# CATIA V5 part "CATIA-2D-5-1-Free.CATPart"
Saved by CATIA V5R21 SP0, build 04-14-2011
Part number: CATIA-2D-5-1-Free
Bounding box of the stored display mesh (mm): x -146.99 to 61.498, y -1 to 1, z -11.995 to 34.997
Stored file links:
  C:\Users\Rasoul Mohammadi\Desktop\CATIA-Free\2D\CATIA-2D-5-1-Free.CATPart
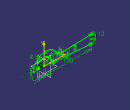
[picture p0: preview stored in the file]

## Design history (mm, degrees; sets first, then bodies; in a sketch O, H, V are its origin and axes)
Body1 (main body)
  Sketch1 on zx-plane, origin (0, 0, 0), H (-1, 0, 0), V (0, 0, 1)
    arc A1 centre (0, 0) radius 22 from (21.9106, 1.9813) to (-21.4243, 5) ccw
    arc A2 centre (5, 0) radius 35 from (36.7634, 14.6999) to (-30, 0) ccw
    point P1 (5, 0)
    arc A3 centre (135, 0) radius 12 from (133.9541, -11.9543) to (134.5812, 11.9927) ccw
    point P2 (135, 0)
    line L1 (26.4545, -2.5493) -> (133.9541, -11.9543)
    point P3 (133.9541, -11.9543)
    line L2 (46.1877, 8.9059) -> (134.5812, 11.9927)
    point P5 (-30, 0)
    line L3 (-30, 0) -> (-14, 0)
    line L4 (-14, 0) -> (-14, 5)
    line L5 (-14, 5) -> (-21.4243, 5)
    point P9 (133.9541, -11.9543)
    arc A4 centre (26.8903, 2.4316) radius 5 from (21.9106, 1.9813) to (26.4545, -2.5493) ccw
    arc A5 centre (45.8387, 18.8998) radius 10 from (36.7634, 14.6999) to (46.1877, 8.9059) ccw
    distance P2 P1 = 130
    angle L1 H = 5
    angle L1 L2 = 7
    radius A3 = 12
    distance P1 V = 5
    distance L4 V = 14
    length L4 = 5
    radius A4 = 5
    radius A5 = 10
    radius A1 = 22
    radius A2 = 35
    coincidence: P1 H, P2 H, P5 H, P9 P3
    tangency: L1 A3, L2 A3, A4 L1, A4 A1, A5 A2, A5 L2
    horizontal: L3 H, L5 H
    vertical: L4 V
